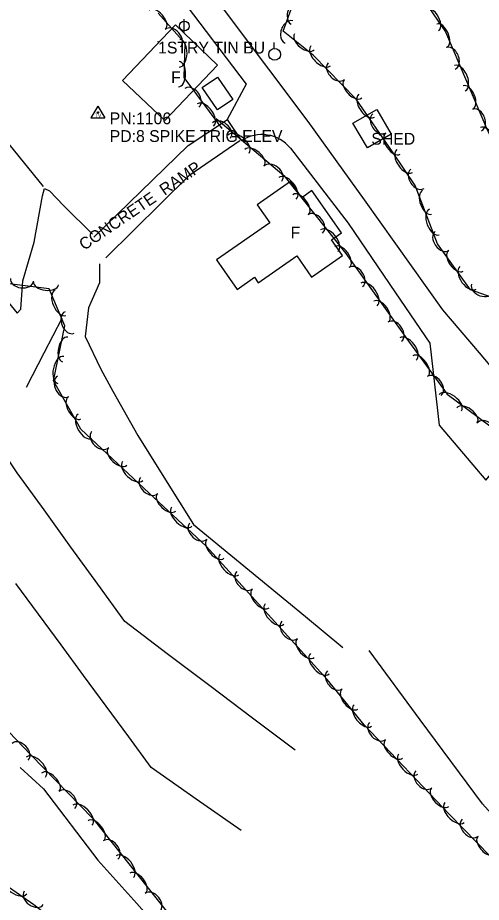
# Model space of a CAD drawing. Extents: x 1451369 to 1458940, y 1868647 to 1875095.
# Drawn here: x 1454551.8 to 1454748.2, y 1871083.8 to 1871458.6 of the extents above; entities that cross this region are included whole.
import ezdxf

# ---------------------------------------------------------------- set-up
doc = ezdxf.new("R2010")
doc.units = 0
for name, color, linetype in [('E_Const Align', 7, 'Continuous'), ('E_Property Line', 7, 'Continuous'), ('E_Row Point', 7, 'Continuous'), ('E_ROW Point Number', 7, 'Continuous'), ('E_Station Offset', 7, 'Continuous'), ('E_Tract Residual', 7, 'Continuous'), ('S_BUILDING_ANNOT', 7, 'Continuous'), ('S_EXIST_ROW', 7, 'Continuous'), ('S_PARKING', 7, 'Continuous'), ('S_PARKING_ANNOT', 7, 'Continuous'), ('S_SECONDARY_CTL_ANNOT', 7, 'Continuous')]:
    doc.layers.add(name, color=color, linetype=linetype)

msp = doc.modelspace()

# ---------------------------------------------------------------- linework, layer by layer
at = {"layer": 'E_Const Align'}
for p, q in [((1454622.37, 1871452.15), (1454622.37, 1871457.94)), ((1454660.53, 1871445.57), (1454660.53, 1871448.05))]:
    msp.add_line(p, q, dxfattribs=at)
for centre, radius in [((1454622.37, 1871455.08), 2.05), ((1454660.67, 1871443.05), 2.5)]:
    msp.add_circle(centre, radius, dxfattribs=at)
at = {"layer": 'E_Property Line'}
for points in [[(1454618.6, 1871455.55), (1454596.26, 1871432.03), (1454614.16, 1871415.03), (1454636.5, 1871438.54)], [(1454636.52, 1871433.47), (1454643.01, 1871423.97), (1454636.47, 1871419.51), (1454629.99, 1871429.01)], [(1454703.9, 1871419.73), (1454709.98, 1871409.22), (1454699.94, 1871403.41), (1454693.86, 1871413.92)], [(1454667.36, 1871389.16), (1454653.28, 1871379.33), (1454658.63, 1871371.67), (1454636.1, 1871355.94), (1454644.78, 1871343.5), (1454652.08, 1871348.59), (1454653.69, 1871346.28), (1454670, 1871357.67), (1454676.25, 1871348.72), (1454689.37, 1871357.88), (1454684.78, 1871364.45), (1454689, 1871367.39), (1454676.48, 1871385.33), (1454672.15, 1871382.31)]]:
    msp.add_lwpolyline(points, close=True, dxfattribs=at)
at = {"layer": 'E_Row Point'}
msp.add_lwpolyline([(1454611.29, 1871448.43), (1454611.29, 1871448.48), (1454611.29, 1871448.43), (1454611.24, 1871448.43), (1454611.29, 1871448.43), (1454611.29, 1871448.38), (1454611.29, 1871448.43), (1454611.34, 1871448.43)], dxfattribs=at)
at = {"layer": 'E_ROW Point Number'}
for points in [[(1454975.93, 1871099.07), (1454929.38, 1871155.93), (1454884.06, 1871212.14), (1454844.07, 1871268.25), (1454818.62, 1871299.3), (1454787.11, 1871333), (1454773.6, 1871342.99), (1454759.62, 1871337.58), (1454743.68, 1871343.3), (1454729.62, 1871362.73), (1454720.26, 1871387.51), (1454710.54, 1871401.75), (1454695.23, 1871424.03), (1454676.94, 1871442.69), (1454664.33, 1871452.85), (1454669.34, 1871466.98), (1454682.96, 1871481.41), (1454700.06, 1871488.27), (1454713.94, 1871480.64), (1454733.1, 1871452.57), (1454750.83, 1871410.87), (1454764.22, 1871384.37), (1454779.73, 1871376.91), (1454787.43, 1871375.32)], [(1454769.59, 1871085.19), (1454734.6, 1871121.15), (1454698.54, 1871159), (1454682.97, 1871178.23), (1454631.67, 1871234.64), (1454607.53, 1871257.1), (1454578.57, 1871284.24), (1454566.94, 1871304.77), (1454571.82, 1871327.97), (1454565.11, 1871343.72), (1454544.85, 1871346.2), (1454524.89, 1871341.15), (1454499.19, 1871366.49), (1454479.99, 1871402.54), (1454460.24, 1871468.96)], [(1454611.35, 1871460.55), (1454622.55, 1871447.83), (1454622.15, 1871433.3), (1454638.22, 1871411.63)], [(1454635.87, 1871415.82), (1454664.55, 1871391.71), (1454690.83, 1871358.7), (1454717.39, 1871321.49), (1454733.73, 1871299.08), (1454760.66, 1871279.22), (1454786.92, 1871267.78), (1454802.36, 1871253.34), (1454835.42, 1871220.54), (1454860.01, 1871184.58), (1454883.47, 1871157.8), (1454907.09, 1871133.65), (1454926.38, 1871112.18), (1454943.47, 1871088.15), (1454957.95, 1871069.45)], [(1454354.98, 1871390.38), (1454371.8, 1871364.92), (1454429.4, 1871303.3), (1454471.21, 1871244.05), (1454496.14, 1871215.11), (1454519.64, 1871185.53), (1454557.32, 1871146.28), (1454583.57, 1871119.27), (1454622.38, 1871070.6), (1454661.94, 1871037.28), (1454703.33, 1871008.9), (1454731.19, 1870986.38), (1454759.84, 1870960.63)], [(1454686.82, 1870930.03), (1454660.52, 1870951.37), (1454644.8, 1870974.62), (1454621.9, 1871011.26), (1454608.54, 1871028.34), (1454594.8, 1871054.46), (1454558.65, 1871082.65), (1454528.1, 1871103.96), (1454501.29, 1871136.27), (1454476.93, 1871172.33), (1454434.4, 1871217.27), (1454411.48, 1871251.51), (1454393.25, 1871278.48), (1454377.48, 1871304.11), (1454353.64, 1871338.7)]]:
    msp.add_lwpolyline(points, dxfattribs=at)
for centre, major_axis, ratio, start_param, end_param in [((1454669.6, 1871461.36), (-1.96, -5.53), 0.550022, 3.141575, 6.283168), ((1454610.93, 1871457.82), (-3.53, 4.01), 0.540647, 3.141593, 6.283185), ((1454726.82, 1871458), (-3.31, 4.85), 0.550076, 3.141593, 6.283185), ((1454666.74, 1871452.54), (-1.66, -4.67), 0.685239, 3.141564, 6.283157), ((1454731.48, 1871450.97), (-2.09, 4.92), 0.540989, 3.141426, 6.283018), ((1454617.54, 1871449.92), (-3.27, 3.72), 0.685244, 3.141593, 6.283185), ((1454673.27, 1871448.37), (4.16, -3.35), 0.540701, 3.141595, 6.283187), ((1454620.31, 1871443.51), (0.16, 5.86), 0.550174, 3.141875, 6.283467), ((1454680.17, 1871442.42), (4.11, -4.19), 0.550089, 3.141589, 6.283182), ((1454735.26, 1871441.39), (-1.94, 4.56), 0.685677, 3.14131, 6.282903), ((1454620.07, 1871434.65), (0.15, 5.34), 0.540792, 3.141866, 6.283458), ((1454686.84, 1871435.99), (3.47, -3.54), 0.685322, 3.141586, 6.283179), ((1454739.13, 1871432.98), (-2.3, 5.4), 0.550374, 3.14142, 6.283013), ((1454625.61, 1871424.64), (-2.95, 3.98), 0.685295, 3.141833, 6.283426), ((1454693.86, 1871428.45), (3.74, -3.82), 0.540708, 3.141589, 6.283182), ((1454742.59, 1871424.82), (-2.09, 4.92), 0.540989, 3.141426, 6.283018), ((1454699.67, 1871421.32), (3.32, -4.84), 0.550085, 3.141577, 6.28317), ((1454631.33, 1871417.36), (-3.49, 4.71), 0.550067, 3.141739, 6.283332), ((1454705.13, 1871413.83), (2.81, -4.08), 0.685317, 3.141567, 6.28316), ((1454746.38, 1871415.24), (-1.94, 4.56), 0.685677, 3.14131, 6.282903), ((1454638.13, 1871410.81), (-3.79, 3.19), 0.685147, 3.141593, 6.283185), ((1454645.39, 1871405.05), (-4.49, 3.78), 0.549949, 3.141593, 6.283185), ((1454750.51, 1871406.8), (-2.65, 5.24), 0.550071, 3.141593, 6.283185), ((1454710.75, 1871405.2), (3.03, -4.41), 0.540704, 3.141578, 6.28317), ((1454652.18, 1871399.34), (-4.09, 3.44), 0.54057, 3.141593, 6.283185), ((1454715.76, 1871397.87), (3.31, -4.85), 0.550106, 3.141563, 6.283156), ((1454659.89, 1871392.51), (-3.79, 3.19), 0.685147, 3.141593, 6.283185), ((1454666.12, 1871386.34), (-3.66, 4.59), 0.549942, 3.141571, 6.283163), ((1454721.2, 1871390.37), (2.79, -4.09), 0.685344, 3.141544, 6.283137), ((1454671.64, 1871379.4), (-3.33, 4.18), 0.540564, 3.141571, 6.283164), ((1454725.24, 1871380.34), (1.89, -5), 0.540686, 3.141593, 6.283185), ((1454728.37, 1871372.04), (2.07, -5.49), 0.550066, 3.141593, 6.283185), ((1454677.85, 1871371.18), (-3.09, 3.88), 0.685139, 3.141557, 6.283149), ((1454683.82, 1871364.1), (-3.66, 4.59), 0.549942, 3.141571, 6.283163), ((1454731.61, 1871364.04), (2.91, -4.01), 0.685307, 3.141593, 6.283185), ((1454689.27, 1871357.24), (-3.11, 4.35), 0.540563, 3.141593, 6.283185), ((1454737.44, 1871355.54), (3.13, -4.33), 0.540697, 3.141593, 6.283185), ((1454695.04, 1871348.7), (-2.88, 4.03), 0.685138, 3.141593, 6.283185), ((1454742.64, 1871348.36), (3.44, -4.75), 0.550077, 3.141593, 6.283185), ((1454553.6, 1871347.53), (4.92, -0.6), 0.685299, 3.141593, 6.283185), ((1454563.8, 1871346.02), (5.31, -0.65), 0.54069, 3.141593, 6.283185), ((1454700.63, 1871341.32), (-3.41, 4.78), 0.549941, 3.141593, 6.283185), ((1454569.92, 1871337.85), (2.3, -5.4), 0.550014, 3.141593, 6.283185), ((1454748.76, 1871344.01), (4.66, -1.67), 0.685298, 3.141593, 6.283185), ((1454705.78, 1871334.1), (-3.11, 4.35), 0.540563, 3.141593, 6.283185), ((1454573.79, 1871329.44), (1.94, -4.56), 0.685229, 3.141593, 6.283185), ((1454711.56, 1871325.57), (-2.88, 4.03), 0.685138, 3.141593, 6.283185), ((1454717.18, 1871318.18), (-3.46, 4.74), 0.549941, 3.141593, 6.283185), ((1454571.89, 1871318.02), (-1.1, -5.23), 0.540646, 3.141593, 6.283185), ((1454570.07, 1871309.34), (-1.21, -5.74), 0.550026, 3.141593, 6.283185), ((1454722.4, 1871311.01), (-3.15, 4.32), 0.540563, 3.141593, 6.283185), ((1454571.05, 1871302.34), (2.44, -4.31), 0.685233, 3.141593, 6.283185), ((1454728.26, 1871302.53), (-2.92, 4), 0.685138, 3.141593, 6.283185), ((1454575.9, 1871293.25), (2.64, -4.65), 0.540638, 3.141593, 6.283185), ((1454735.08, 1871295.44), (-4.72, 3.48), 0.549953, 3.141593, 6.283185), ((1454742.22, 1871290.18), (-4.3, 3.17), 0.540575, 3.141593, 6.283185), ((1454580.27, 1871285.53), (2.89, -5.11), 0.550017, 3.141593, 6.283185), ((1454750.36, 1871283.86), (-3.99, 2.94), 0.685153, 3.141593, 6.283185), ((1454586.74, 1871279.84), (3.62, -3.39), 0.685251, 3.141593, 6.283185), ((1454594.08, 1871272.61), (3.9, -3.66), 0.540652, 3.141593, 6.283185), ((1454600.55, 1871266.55), (4.28, -4.01), 0.550032, 3.141593, 6.283185), ((1454607.49, 1871260.41), (3.62, -3.39), 0.685251, 3.141593, 6.283185), ((1454614.84, 1871253.2), (3.91, -3.64), 0.540652, 3.141593, 6.283185), ((1454621.33, 1871247.16), (4.3, -4), 0.550032, 3.141593, 6.283185), ((1454628.29, 1871241.04), (3.63, -3.38), 0.685251, 3.141593, 6.283185), ((1454635.57, 1871233.5), (3.6, -3.96), 0.540647, 3.141595, 6.283187), ((1454641.54, 1871226.94), (3.95, -4.34), 0.550027, 3.141595, 6.283187), ((1454647.96, 1871220.27), (3.33, -3.67), 0.685245, 3.141596, 6.283189), ((1454654.7, 1871212.47), (3.6, -3.96), 0.540647, 3.141595, 6.283187), ((1454660.67, 1871205.91), (3.95, -4.34), 0.550027, 3.141595, 6.283187), ((1454667.09, 1871199.24), (3.33, -3.67), 0.685245, 3.141596, 6.283189), ((1454673.83, 1871191.44), (3.6, -3.96), 0.540647, 3.141595, 6.283187), ((1454679.79, 1871184.88), (3.95, -4.34), 0.550027, 3.141595, 6.283187), ((1454686.21, 1871178.02), (3.12, -3.85), 0.685247, 3.141665, 6.283258), ((1454692.49, 1871169.84), (3.36, -4.16), 0.540649, 3.141636, 6.283228), ((1454698.06, 1871162.95), (3.69, -4.56), 0.550028, 3.141637, 6.28323), ((1454704.31, 1871156.39), (3.41, -3.58), 0.687066, 3.14289, 6.284482), ((1454552.82, 1871147.54), (-3.43, 3.57), 0.685149, 3.141593, 6.283185), ((1454711.21, 1871148.77), (3.68, -3.86), 0.542085, 3.142358, 6.28395), ((1454559.45, 1871141.05), (-4.09, 4.21), 0.54995, 3.141593, 6.283185), ((1454717.31, 1871142.37), (4.04, -4.24), 0.551489, 3.142383, 6.283975), ((1454565.63, 1871134.69), (-3.73, 3.83), 0.540572, 3.141593, 6.283185), ((1454723.87, 1871135.86), (3.41, -3.58), 0.687066, 3.14289, 6.284482), ((1454572.62, 1871127.12), (-3.45, 3.55), 0.685149, 3.141593, 6.283185), ((1454730.77, 1871128.25), (3.68, -3.86), 0.542085, 3.142358, 6.28395), ((1454579.26, 1871120.66), (-4.09, 4.21), 0.54995, 3.141593, 6.283185), ((1454736.87, 1871121.86), (4.09, -4.21), 0.550029, 3.141594, 6.283187), ((1454584.95, 1871114.15), (-3.33, 4.18), 0.540574, 3.141593, 6.283185), ((1454743.51, 1871115.41), (3.46, -3.55), 0.685247, 3.141595, 6.283188), ((1454591.16, 1871105.93), (-3.09, 3.87), 0.685152, 3.141593, 6.283185), ((1454750.51, 1871107.84), (3.73, -3.83), 0.540649, 3.141594, 6.283187), ((1454597.14, 1871098.85), (-3.66, 4.59), 0.549952, 3.141593, 6.283185), ((1454602.67, 1871091.92), (-3.33, 4.18), 0.540574, 3.141593, 6.283185), ((1454550.81, 1871090.71), (4.81, -3.36), 0.549953, 3.141593, 6.283185), ((1454558.56, 1871085.62), (4.06, -2.84), 0.685153, 3.141593, 6.283185), ((1454608.89, 1871083.7), (-3.09, 3.87), 0.685152, 3.141593, 6.283185)]:
    msp.add_ellipse(centre, major_axis=major_axis, ratio=ratio, start_param=start_param, end_param=end_param, dxfattribs=at)
at = {"layer": 'E_Station Offset'}
for p, q in [((1454585.78, 1871421.06), (1454582.77, 1871416.11)), ((1454585.78, 1871421.06), (1454588.73, 1871416.11)), ((1454582.77, 1871416.11), (1454588.73, 1871416.11))]:
    msp.add_line(p, q, dxfattribs=at)
for radius in [0.311, 0.183, 0.103]:
    msp.add_circle((1454585.78, 1871418.45), radius, dxfattribs=at)
at = {"layer": 'E_Tract Residual'}
for points in [[(1454479.45, 1871459.48), (1454487.96, 1871440.08), (1454496.47, 1871420.69), (1454504.96, 1871408.8), (1454513.44, 1871396.91), (1454521.92, 1871385.02), (1454530.41, 1871373.12), (1454534.3, 1871363.17), (1454534.74, 1871353.7), (1454543.14, 1871343.58), (1454551.55, 1871333.45), (1454553.08, 1871335.1), (1454553.96, 1871347.1), (1454558.84, 1871363.47), (1454562.32, 1871383.14), (1454563.1, 1871386.17), (1454565.32, 1871385.29), (1454571.29, 1871378.9), (1454583.47, 1871366.9)], [(1454586.48, 1871354.36), (1454586.45, 1871346.26), (1454581.86, 1871335.7), (1454580.44, 1871323.54), (1454587.04, 1871309.7), (1454592.17, 1871300.3), (1454602.65, 1871281.6), (1454614.46, 1871262.77), (1454626.26, 1871243.93), (1454642.1, 1871230.89), (1454657.93, 1871217.85), (1454673.76, 1871204.81), (1454689.6, 1871191.76)], [(1454858.26, 1871027.57), (1454824.63, 1871053.16), (1454795.51, 1871077.11), (1454774.76, 1871096.49), (1454748.73, 1871125.57), (1454722.31, 1871161.05), (1454700.69, 1871190.53)], [(1454552.87, 1871140.84), (1454562.72, 1871131.88), (1454585.7, 1871101.57), (1454602.23, 1871083.27), (1454627.98, 1871054.14), (1454644.77, 1871031.33), (1454666.33, 1871011.02), (1454685.1, 1870997.54), (1454697.09, 1870985.37), (1454731.35, 1870957.49)]]:
    msp.add_lwpolyline(points, dxfattribs=at)
at = {"layer": 'S_EXIST_ROW'}
for points in [[(1454562.7, 1871387.08), (1454548.13, 1871404.98), (1454535.85, 1871424.34), (1454530.7, 1871442.21), (1454525.54, 1871460.07), (1454519.63, 1871483.17), (1454512.82, 1871496.11)], [(1454669.39, 1871148.22), (1454651.32, 1871161.85), (1454633.26, 1871175.48), (1454615.19, 1871189.12), (1454597.13, 1871202.75), (1454585.74, 1871218.51), (1454574.36, 1871234.27), (1454562.98, 1871250.04), (1454551.59, 1871265.8), (1454537.54, 1871286.41), (1454523.49, 1871307.02), (1454510.77, 1871308.95), (1454498.06, 1871310.88), (1454488.14, 1871326.29), (1454478.22, 1871341.7), (1454468.29, 1871357.11), (1454458.37, 1871372.52), (1454456.11, 1871389.06), (1454453.85, 1871405.59), (1454451.59, 1871422.12), (1454449.33, 1871438.65), (1454436.97, 1871447.74), (1454424.6, 1871456.83), (1454412.24, 1871465.92)], [(1454555.46, 1871302.04), (1454563.02, 1871316.64), (1454570.57, 1871331.23)], [(1454646.52, 1871114.18), (1454627.46, 1871127.55), (1454608.4, 1871140.91), (1454598.84, 1871153.9), (1454589.28, 1871166.89), (1454579.72, 1871179.88), (1454570.16, 1871192.87), (1454560.6, 1871205.86), (1454551.04, 1871218.85)]]:
    msp.add_lwpolyline(points, dxfattribs=at)
at = {"layer": 'S_PARKING'}
for points in [[(1454667.4, 1871403.25), (1454691.79, 1871371.47), (1454711.91, 1871341.99), (1454726.42, 1871320.72), (1454730.31, 1871286), (1454750.1, 1871262.65), (1454771.52, 1871288.12), (1454747.41, 1871316.57), (1454731.99, 1871334.79), (1454698.75, 1871381.43), (1454674.92, 1871414.59), (1454641.56, 1871458.91), (1454629.89, 1871474.76)], [(1454620.49, 1871467.53), (1454648.64, 1871430.5), (1454640.49, 1871415.41), (1454646.62, 1871406.42)], [(1454584.1, 1871365.61), (1454624.09, 1871404.38), (1454640.65, 1871415.52)], [(1454645.9, 1871406.47), (1454624.28, 1871391.59), (1454589.13, 1871356.8)]]:
    msp.add_lwpolyline(points, dxfattribs=at)
msp.add_ellipse((1454655.3, 1871393.58), major_axis=(-14.01, 6.66), ratio=0.998226, start_param=4.260389, end_param=5.749542, dxfattribs=at)

# ---------------------------------------------------------------- texts
at = {"layer": 'E_Station Offset'}
msp.add_text('TV', height=1.5, rotation=360, dxfattribs=at).set_placement((1454584.58, 1871416.44))
at = {"layer": 'S_BUILDING_ANNOT'}
for s, height, p in [('1STRY TIN BU', 5, (1454611.29, 1871443.43)), ('F', 5, (1454616.8, 1871430.92)), ('SHED', 5.001, (1454701.65, 1871404.8)), ('F', 5, (1454667.45, 1871365.05))]:
    msp.add_text(s, height=height, dxfattribs=at).set_placement(p)
at = {"layer": 'S_PARKING_ANNOT'}
msp.add_text('CONCRETE  RAMP', height=5.0004, rotation=34.3129, dxfattribs=at).set_placement((1454579.96, 1871359.8))
at = {"layer": 'S_SECONDARY_CTL_ANNOT'}
for s, p in [('PN:1106', (1454590.78, 1871413.45)), ('PD:8 SPIKE TRIG ELEV', (1454590.78, 1871405.95))]:
    msp.add_text(s, height=5, dxfattribs=at).set_placement(p)

doc.saveas('drawing.dxf')
